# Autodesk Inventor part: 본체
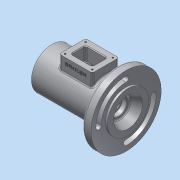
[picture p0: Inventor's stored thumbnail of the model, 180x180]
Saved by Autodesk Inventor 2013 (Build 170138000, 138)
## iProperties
Created: 2017-05
Part Number: 본체
Material: 알루미늄 6061
Document SubType Name: Modeling
Designer: dgall
Density: 2.71 g/cm^3
Mass: 720.492 g
Surface Area: 632.188 cm^2
Volume: 265.864 cm^3
Author: dgall
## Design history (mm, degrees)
sketch "스케치1"
  geometry: L1 (-57.5, 0)-(57.5, 0); L2 (-57.5, 21)-(-57.5, 31); L3 (-57.5, 31)-(41.5, 31); L4 (41.5, 31)-(41.5, 53); L5 (41.5, 53)-(54.5, 53); L6 (54.5, 53)-(54.5, 31); L7 (54.5, 31)-(57.5, 31); L8 (57.5, 31)-(57.5, 22); L9 (57.5, 22)-(45.318, 16.779); L10 (43.5, 14.022)-(43.5, 12.904); L11 (28.5, 16.5)-(28.5, 17.2); L12 (28.2, 17.5)-(17.5, 17.5); L13 (17.5, 17.5)-(17.5, 23); L14 (14.5, 26)-(-17.5, 26); L15 (-20.5, 23)-(-20.5, 17.5); L16 (-20.5, 17.5)-(-31.5, 17.5); L17 (-31.5, 17.5)-(-31.5, 18.5); L18 (-31.5, 18.5)-(-33.25, 18.5); L19 (-33.25, 18.5)-(-33.25, 17.5); L20 (-33.25, 17.5)-(-36.5, 17.5); L21 (-36.5, 17.5)-(-36.5, 20); L22 (-36.5, 20)-(-45.5, 20); L23 (-45.5, 20)-(-45.5, 24); L24 (-45.5, 24)-(-48.5, 24); L25 (-48.5, 24)-(-48.5, 21); L26 (-48.5, 21)-(-57.5, 21); L27 (36.2, 12.2)-(36.2, 10); L28 (36.2, 10)-(33.5, 10); L29 (33.5, 10)-(33.5, 13.5); L30 (30.5, 16.5)-(28.5, 16.5); L31 (36.5, 12.5)-(42.8, 12.5); L32 (42.8, 12.5)-(43.5, 12.904); A1 r 0.3 centre (36.5, 12.2) between (36.5, 12.5) and (36.2, 12.2); A2 r 3 centre (-17.5, 23) between (-17.5, 26) and (-20.5, 23); A3 r 3 centre (14.5, 23) between (17.5, 23) and (14.5, 26); A4 r 3 centre (30.5, 13.5) between (33.5, 13.5) and (30.5, 16.5); A5 r 3 centre (46.5, 14.022) between (45.318, 16.779) and (43.5, 14.022); A6 r 0.3 centre (28.2, 17.2) between (28.5, 17.2) and (28.2, 17.5); 7 further points
  constraints: 64 end point, 14 parallel, 12 point on circle, 12 tangent, 10 point on line, 8 perpendicular, 6 centre point, 2 equal radius, 2 vertical alignment, 1 coincident, 1 horizontal, 1 horizontal alignment, 1 midpoint
  dimensions: "d0" = 42 diameter of L26 L1; "d2" = 48 diameter of L24 L1; "d3" = 62 diameter of L3 L1; "d4" = 9 distance of L25.end L2.start; "d5" = 3 distance of L23.end L24.end; "d8" = 37 diameter of L18 L1; "d9" = 1.75 distance of L17.end L18.end; "d10" = 26 distance between parallel lines of L2 L17; "d11" = 21 distance between parallel lines of L2 L21; "d12" = 11 distance of L15.end L16.end; "d13" = 35 diameter of L16 L1; "d14" = 52 diameter of L14 L1; "d15" = 11 distance of point (28.5, 17.5) L12.end; "d16" = 32 diameter of point (43.5, 16) L1; "d17" = 14 horizontal distance of L8.end point (43.5, 16); "d20" = 44 diameter of L8.end L1; "d21" = 62 diameter of L7 L1; "d22" = 106 diameter of L5 L1; "d24" = 2.7 distance of L27.end L28.end; "d25" = 5 distance of point (33.5, 16.5) L11.start; "d27" = 30 deg angle of L31 L32; "d28" = 0.7 horizontal distance of L31.end L10.end; "d29" = 7.3 distance between parallel lines of L10 L27; "d30" = 0.3 radius of A1; "d31" = 25 diameter of L31 L1; "d32" = 20 diameter of L28 L1; "d33" = 115 distance of L1.start L1.end; "d34" = 13 distance of L4.end L5.end; "d35" = 3 distance of L6.end L7.end; "d36" = 40 diameter of L22 L1; "d37" = 35 diameter of L20 L1; "d38" = 38 distance of point (17.5, 26) point (-20.5, 26); "d39" = 33 diameter of L30 L1; "d40" = 3 radius of A2; "d41" = 3 radius of A4; "d126" = 0.3 radius of A6
revolve "회전1" sketch "스케치1" stored, may be unused: angle "d42" = 90 deg
fillet "모깎기1" dims "d48" = 3
node "작업 평면1"
sketch "스케치2"
  geometry: L1 (-23.5, 20)-(26.5, 20); L2 (26.5, 20)-(26.5, -20); L3 (26.5, -20)-(-23.5, -20); L4 (-23.5, -20)-(-23.5, 20); L5 (57.5, 31)-(57.5, -31) reference; L6 (-14.5, 11)-(17.5, 11); L7 (17.5, 11)-(17.5, -11); L8 (17.5, -11)-(-14.5, -11); L9 (-14.5, -11)-(-14.5, 11); 5 further points
  constraints: 16 end point, 4 midpoint, 4 parallel, 2 horizontal, 2 horizontal alignment, 2 perpendicular, 1 vertical alignment
  dimensions: "d50" = 50 distance of L2.end L3.end; "d52" = 40 distance of L1.end L2.end; "d53" = 31 distance between parallel lines of L5 L2; "d54" = 32 distance of L7.end L8.end; "d55" = 22 distance of L6.end L7.end
extrude "돌출1" join sketch "스케치2" stored distance "d56" = 10; taper "d57" = 0 deg
extrude "돌출2" cut sketch "스케치2" distance "d58" = 40; taper "d59" = 0 deg
fillet "모깎기2" dims "d60" = 3
fillet "모깎기3" dims "d61" = 3
fillet "모깎기4" dims "d62" = 3
sketch "스케치3"
  geometry: L1 (-26.5, -17)-(-26.5, 17) reference; L2 (20.5, -20)-(-23.5, -20) reference; L3 (23.5, 17)-(23.5, -17) reference; L4 (-23.5, 20)-(20.5, 20) reference; L5 (-26.5, 0)-(23.5, 0); L6 (-1.5, 20)-(-1.5, -20); L7 (-57.5, -31)-(-57.5, 31) reference; 2 further points
  constraints: 4 end point, 4 midpoint, 1 perpendicular
  dimensions: "d81" = 15.5 vertical distance of point (0, 0) point (19, 15.5); "d82" = 56 distance between parallel lines of L7 L6; "d83" = 20.5 distance from line of point (19, 15.5) L6
hole "구멍2" sketch "스케치3" at (19, 15.5) diameter "d84" = 2.459; stored, may be unused: countersink angle "d88" = 90 deg, drill point angle "d90" = 118 deg; dims "d85" = 6, "d86" = 4, "d87" = 2, "d89" = 8
sketch "스케치4"
  geometry: C1 r 31 at (0, 0) reference; C2 r 53 at (0, 0) reference; A1 r 41.5 centre (0, 0) between (0, 41.5) and (-41.5, 0); A2 r 4 centre (0, 41.5) between (0, 37.5) and (0, 45.5); A3 r 45.5 centre (0, 0) between (0, 45.5) and (-45.5, 0); A4 r 37.5 centre (0, 0) between (0, 37.5) and (-37.5, 0); A5 r 4 centre (-41.5, 0) between (-45.5, 0) and (-37.5, 0)
  constraints: 10 point on circle, 5 centre point, 3 coincident, 2 tangent, 2 vertical alignment, 1 horizontal alignment
  dimensions: "d97" = 41.5 radius of A1; "d99" = 4 radius of A2
extrude "돌출3" cut sketch "스케치4" distance "d100" = 20; taper "d101" = 0 deg
sketch "스케치5"
  geometry: L1 (44, 0)-(0, 0) reference; L2 (-34, -75)-(-34, -13) reference; 2 further points
  constraints: 1 other
  dimensions: "d105" = 56 distance from line of L2 point (22, -8); "d106" = 8 distance from line of point (22, -8) L1
feature "엠보싱1" sketch "스케치5" dims "d14" = 52, "d107" = 0.5, "d108" = 0
chamfer "모따기2" distance "d109" = 1; stored, may be unused: second distance "d110" = 2, angle "d111" = 45 deg
sketch "스케치6"
  geometry: C1 r 21 at (0, 0) reference
extrude "돌출4" join sketch "스케치6" distance "d112" = 9; taper "d113" = 0 deg
hole "구멍3" diameter "d116" = 40.376; stored, may be unused: countersink angle "d120" = 90 deg, drill point angle "d122" = 118 deg; dims "d114" = 10, "d115" = 10, "d117" = 9, "d118" = 4, "d119" = 2, "d121" = 9
chamfer "모따기3" distance "d123" = 1; stored, may be unused: second distance "d124" = 2, angle "d125" = 45 deg
chamfer "모따기4" distance "d127" = 1; stored, may be unused: second distance "d128" = 2, angle "d129" = 45 deg
node "솔리드1"
pattern_linear "직사각형 패턴2" dims "d93" = 31, "d96" = 41
pattern_circular "원형 패턴1" dims angle "d103" = 360 deg
other parameters: "d49" = 44
